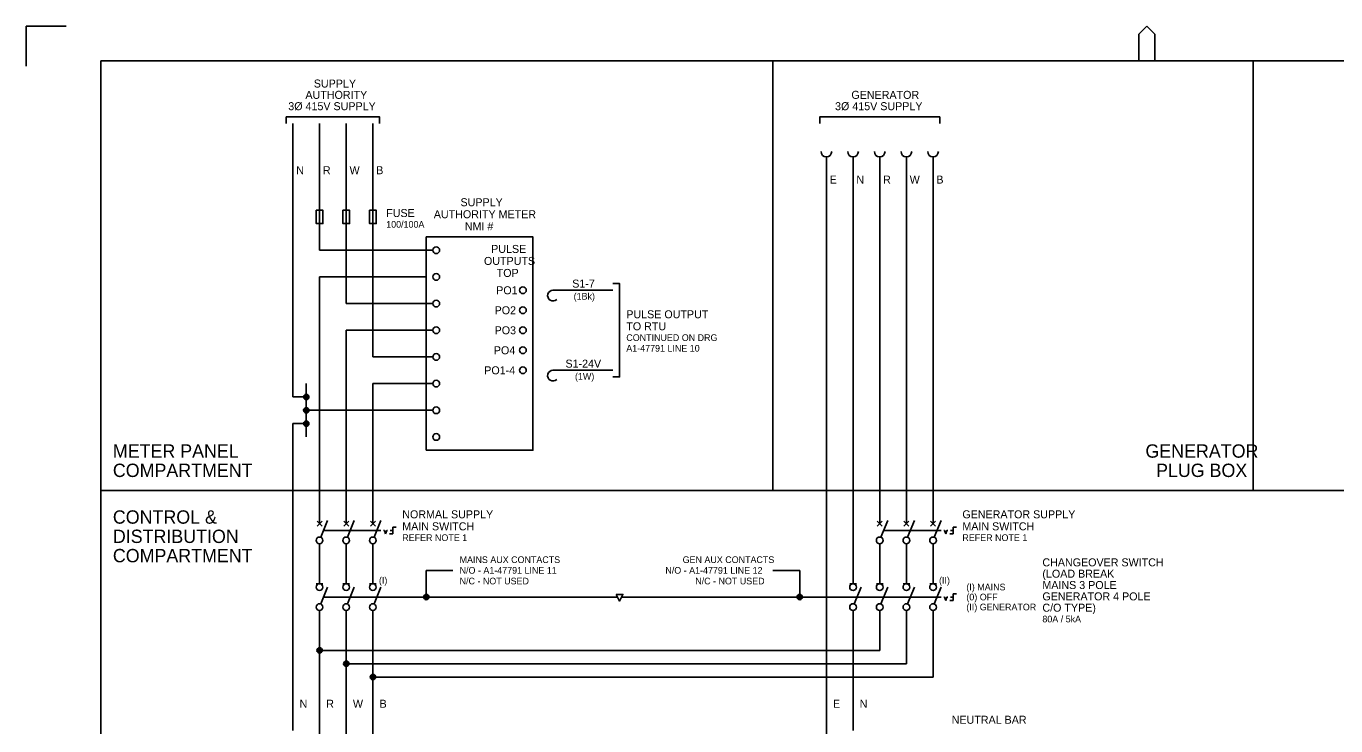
# Model space of a CAD drawing. Extents: x 0 to 841, y 0 to 594.
# Drawn here: x 0 to 491, y 331.7 to 594 of the extents above; entities that cross this region are included whole.
import ezdxf

# ---------------------------------------------------------------- set-up
doc = ezdxf.new("R2010")
doc.units = 0
for name, color, linetype in [('A1BORDER', 7, 'Continuous'), ('Level 1', 7, 'Continuous'), ('Level 10', 7, 'Continuous')]:
    doc.layers.add(name, color=color, linetype=linetype)

msp = doc.modelspace()

# ---------------------------------------------------------------- linework, layer by layer
at = {"layer": 'A1BORDER'}
for p, q in [((0, 594), (15, 594)), ((0, 579), (0, 594)), ((417.19, 591), (420.19, 594)), ((417.19, 581), (417.19, 591)), ((423.19, 591), (420.19, 594)), ((423.19, 581), (423.19, 591)), ((28, 581), (829, 581)), ((28, 581), (28, 15))]:
    msp.add_line(p, q, dxfattribs=at)
at = {"layer": 'Level 1'}
for p, q in [((280, 420), (280, 581)), ((460, 420), (460, 581)), ((100, 455), (100, 557.5)), ((110, 510), (110, 557.5)), ((120, 490), (120, 557.5)), ((130, 470), (130, 557.5)), ((300, 320), (300, 545)), ((310, 385), (310, 545)), ((320, 410), (320, 545)), ((330, 410), (330, 545)), ((340, 410), (340, 545)), ((153.75, 511.25), (153.75, 511.25)), ((152.5, 510), (110, 510)), ((153.75, 508.75), (153.75, 508.75)), ((153.75, 501.25), (153.75, 501.25)), ((150, 500), (110, 500)), ((110, 500), (110, 410)), ((153.75, 498.75), (153.75, 498.75)), ((186.25, 496.25), (186.25, 496.25)), ((153.75, 491.25), (153.75, 491.25)), ((186.25, 493.75), (186.25, 493.75)), ((197.5, 495), (220, 495)), ((152.5, 490), (120, 490)), ((153.75, 488.75), (153.75, 488.75)), ((186.25, 488.75), (186.25, 488.75)), ((186.25, 486.25), (186.25, 486.25)), ((153.75, 481.25), (153.75, 481.25)), ((186.25, 481.25), (186.25, 481.25)), ((152.5, 480), (120, 480)), ((120, 480), (120, 410)), ((153.75, 478.75), (153.75, 478.75)), ((186.25, 478.75), (186.25, 478.75)), ((186.25, 473.75), (186.25, 473.75)), ((152.5, 470), (130, 470)), ((153.75, 471.25), (153.75, 471.25)), ((153.75, 468.75), (153.75, 468.75)), ((186.25, 471.25), (186.25, 471.25)), ((186.25, 466.25), (186.25, 466.25)), ((186.25, 463.75), (186.25, 463.75)), ((197.5, 465), (220, 465)), ((105, 460), (105, 440)), ((152.5, 460), (130, 460)), ((130, 460), (130, 410)), ((153.75, 461.25), (153.75, 461.25)), ((153.75, 458.75), (153.75, 458.75)), ((100, 455), (105, 455)), ((152.5, 450), (105, 450)), ((153.75, 451.25), (153.75, 451.25)), ((153.75, 448.75), (153.75, 448.75)), ((100, 330), (100, 445)), ((105, 445), (100, 445)), ((153.75, 441.25), (153.75, 441.25)), ((153.75, 438.75), (153.75, 438.75)), ((28, 420), (829, 420)), ((109.06, 408.44), (110.94, 406.56)), ((110.94, 408.44), (109.06, 406.56)), ((110, 407.5), (110, 410)), ((110.46, 402.41), (113, 408.75)), ((119.06, 408.44), (120.94, 406.56)), ((120.94, 408.44), (119.06, 406.56)), ((120, 407.5), (120, 410)), ((120.46, 402.41), (123, 408.75)), ((129.06, 408.44), (130.94, 406.56)), ((130.94, 408.44), (129.06, 406.56)), ((130, 407.5), (130, 410)), ((130.46, 402.41), (133, 408.75)), ((319.06, 408.44), (320.94, 406.56)), ((320.94, 408.44), (319.06, 406.56)), ((320, 407.5), (320, 410)), ((320.46, 402.41), (323, 408.75)), ((329.06, 408.44), (330.94, 406.56)), ((330.94, 408.44), (329.06, 406.56)), ((330, 407.5), (330, 410)), ((330.46, 402.41), (333, 408.75)), ((339.06, 408.44), (340.94, 406.56)), ((340.94, 408.44), (339.06, 406.56)), ((340, 407.5), (340, 410)), ((340.46, 402.41), (343, 408.75)), ((111.5, 405), (131.5, 405)), ((321.5, 405), (341.5, 405)), ((110, 400), (110, 385)), ((120, 400), (120, 385)), ((130, 400), (130, 385)), ((320, 400), (320, 385)), ((330, 400), (330, 385)), ((340, 400), (340, 385)), ((150, 380), (150, 390)), ((150, 390), (160, 390)), ((280, 390), (290, 390)), ((290, 380), (290, 390)), ((108.75, 385), (111.25, 385)), ((110.46, 377.41), (113, 383.75)), ((118.75, 385), (121.25, 385)), ((120.46, 377.41), (123, 383.75)), ((128.75, 385), (131.25, 385)), ((130.46, 377.41), (133, 383.75)), ((308.75, 385), (311.25, 385)), ((310.46, 377.41), (313, 383.75)), ((318.75, 385), (321.25, 385)), ((320.46, 377.41), (323, 383.75)), ((328.75, 385), (331.25, 385)), ((330.46, 377.41), (333, 383.75)), ((338.75, 385), (341.25, 385)), ((340.46, 377.41), (343, 383.75)), ((111.5, 380), (221.75, 380)), ((149.01, 380.1), (150.99, 380.1)), ((149.02, 379.8), (150.98, 379.8)), ((149.08, 380.4), (150.92, 380.4)), ((149.13, 379.5), (150.87, 379.5)), ((149.29, 380.7), (150.71, 380.7)), ((149.4, 379.2), (150.6, 379.2)), ((150, 381), (150, 381)), ((223.25, 380), (341.5, 380)), ((289.01, 380.1), (290.99, 380.1)), ((289.02, 379.8), (290.98, 379.8)), ((289.08, 380.4), (290.92, 380.4)), ((289.13, 379.5), (290.87, 379.5)), ((289.29, 380.7), (290.71, 380.7)), ((289.4, 379.2), (290.6, 379.2)), ((290, 381), (290, 381)), ((110, 375), (110, 310)), ((120, 375), (120, 300)), ((130, 375), (130, 290)), ((310, 330), (310, 375)), ((320, 360), (320, 375)), ((330, 355), (330, 375)), ((340, 350), (340, 375)), ((109.01, 360.1), (110.99, 360.1)), ((109.02, 359.8), (110.98, 359.8)), ((109.08, 360.4), (110.92, 360.4)), ((109.13, 359.5), (110.87, 359.5)), ((109.29, 360.7), (110.71, 360.7)), ((109.4, 359.2), (110.6, 359.2)), ((110, 361), (110, 361)), ((320, 360), (110, 360)), ((119.01, 355.1), (120.99, 355.1)), ((119.02, 354.8), (120.98, 354.8)), ((119.08, 355.4), (120.92, 355.4)), ((119.13, 354.5), (120.87, 354.5)), ((119.29, 355.7), (120.71, 355.7)), ((119.4, 354.2), (120.6, 354.2)), ((120, 356), (120, 356)), ((120, 355), (330, 355)), ((129.01, 350.1), (130.99, 350.1)), ((129.02, 349.8), (130.98, 349.8)), ((129.08, 350.4), (130.92, 350.4)), ((129.13, 349.5), (130.87, 349.5)), ((129.29, 350.7), (130.71, 350.7)), ((129.4, 349.2), (130.6, 349.2)), ((130, 351), (130, 351)), ((130, 350), (340, 350))]:
    msp.add_line(p, q, dxfattribs=at)
for points in [[(97.5, 557.5), (97.5, 560), (132.5, 560), (132.5, 557.5)], [(297.5, 557.5), (297.5, 560), (342.5, 560), (342.5, 557.5)], [(220, 497.5), (222.5, 497.5), (222.5, 462.5), (220, 462.5)]]:
    msp.add_lwpolyline(points, dxfattribs=at)
for points in [[(150, 435), (190, 435), (190, 515), (150, 515)], [(221.25, 381), (222.5, 378.5), (223.75, 381)]]:
    msp.add_lwpolyline(points, close=True, dxfattribs=at)
for centre, radius in [((110, 401.25), 1.25), ((120, 401.25), 1.25), ((130, 401.25), 1.25), ((320, 401.25), 1.25), ((330, 401.25), 1.25), ((340, 401.25), 1.25), ((110, 383.75), 1.25), ((120, 383.75), 1.25), ((130, 383.75), 1.25), ((310, 383.75), 1.25), ((320, 383.75), 1.25), ((330, 383.75), 1.25), ((340, 383.75), 1.25), ((150, 380), 1), ((290, 380), 1), ((110, 376.25), 1.25), ((120, 376.25), 1.25), ((130, 376.25), 1.25), ((310, 376.25), 1.25), ((320, 376.25), 1.25), ((330, 376.25), 1.25), ((340, 376.25), 1.25), ((110, 360), 1), ((120, 355), 1), ((130, 350), 1)]:
    msp.add_circle(centre, radius, dxfattribs=at)
for centre in [(197.5, 493), (197.5, 463)]:
    msp.add_arc(centre, 2, 90, 315, dxfattribs=at)
at = {"layer": 'Level 10'}
for p, q in [((104.01, 455.1), (105.99, 455.1)), ((104.02, 454.8), (105.98, 454.8)), ((104.08, 455.4), (105.92, 455.4)), ((104.13, 454.5), (105.87, 454.5)), ((104.29, 455.7), (105.71, 455.7)), ((104.4, 454.2), (105.6, 454.2)), ((105, 456), (105, 456)), ((104.01, 450.1), (105.99, 450.1)), ((104.02, 449.8), (105.98, 449.8)), ((104.08, 450.4), (105.92, 450.4)), ((104.13, 449.5), (105.87, 449.5)), ((104.29, 450.7), (105.71, 450.7)), ((104.4, 449.2), (105.6, 449.2)), ((105, 451), (105, 451)), ((104.01, 445.1), (105.99, 445.1)), ((104.02, 444.8), (105.98, 444.8)), ((104.08, 445.4), (105.92, 445.4)), ((104.13, 444.5), (105.87, 444.5)), ((104.29, 445.7), (105.71, 445.7)), ((104.4, 444.2), (105.6, 444.2)), ((105, 446), (105, 446)), ((131.5, 405), (133, 405)), ((134, 405), (134.33, 405)), ((134.75, 403.75), (134.33, 405)), ((134.75, 403.75), (135.17, 405)), ((135.5, 405), (135.17, 405)), ((136.25, 403.75), (137.5, 403.75)), ((136.5, 405), (137.5, 405)), ((137.5, 403.75), (137.5, 406.25)), ((137.5, 406.25), (138.75, 406.25)), ((341.5, 405), (343, 405)), ((344, 405), (344.33, 405)), ((344.75, 403.75), (344.33, 405)), ((344.75, 403.75), (345.17, 405)), ((345.5, 405), (345.17, 405)), ((346.25, 403.75), (347.5, 403.75)), ((346.5, 405), (347.5, 405)), ((347.5, 403.75), (347.5, 406.25)), ((347.5, 406.25), (348.75, 406.25)), ((341.5, 380), (343, 380)), ((344, 380), (344.33, 380)), ((344.75, 378.75), (344.33, 380)), ((344.75, 378.75), (345.17, 380)), ((345.5, 380), (345.17, 380)), ((346.25, 378.75), (347.5, 378.75)), ((346.5, 380), (347.5, 380)), ((347.5, 378.75), (347.5, 381.25)), ((347.5, 381.25), (348.75, 381.25))]:
    msp.add_line(p, q, dxfattribs=at)
for points in [[(110, 520), (111.25, 520), (111.25, 525), (108.75, 525), (108.75, 520), (110, 520)], [(120, 520), (121.25, 520), (121.25, 525), (118.75, 525), (118.75, 520), (120, 520)], [(130, 520), (131.25, 520), (131.25, 525), (128.75, 525), (128.75, 520), (130, 520)]]:
    msp.add_lwpolyline(points, dxfattribs=at)
for centre, radius in [((153.75, 510), 1.25), ((153.75, 500), 1.25), ((186.25, 495), 1.25), ((153.75, 490), 1.25), ((186.25, 487.5), 1.25), ((153.75, 480), 1.25), ((186.25, 480), 1.25), ((186.25, 472.5), 1.25), ((153.75, 470), 1.25), ((186.25, 465), 1.25), ((153.75, 460), 1.25), ((105, 455), 1), ((105, 450), 1), ((153.75, 450), 1.25), ((105, 445), 1), ((153.75, 440), 1.25)]:
    msp.add_circle(centre, radius, dxfattribs=at)
for centre in [(300, 547), (310, 547), (320, 547), (330, 547), (340, 547)]:
    msp.add_arc(centre, 2, 180, 0, dxfattribs=at)

# ---------------------------------------------------------------- texts
at = {"layer": 'Level 1'}
for s, height, p in [('AUTHORITY', 3, (104.69, 566.76)), ('SUPPLY', 3, (107.83, 571.01)), ('GENERATOR', 3, (309.39, 566.76)), ('3Ø 415V SUPPLY', 3, (98.27, 562.51)), ('3Ø 415V SUPPLY', 3, (303.27, 562.51)), ('N', 3, (101.25, 538.5)), ('R', 3, (111.25, 538.5)), ('W', 3, (121.25, 538.5)), ('B', 3, (131.25, 538.5)), ('E', 3, (301.25, 535)), ('N', 3, (311.25, 535)), ('R', 3, (321.25, 535)), ('W', 3, (331.25, 535)), ('B', 3, (341.25, 535)), ('FUSE', 3, (134.98, 522.46)), ('SUPPLY', 3, (162.83, 526.5)), ('100/100A', 2.5, (134.98, 518.46)), ('AUTHORITY METER', 3, (152.82, 522)), ('NMI #', 3, (164.47, 517.5)), ('PULSE', 3, (174.32, 509)), ('OUTPUTS', 3, (171.63, 504.5)), ('TOP', 3, (176.41, 500)), ('PO1', 3, (176.22, 493.5)), ('S1-7', 3, (204.72, 496)), ('(1Bk)', 2.5, (205.26, 491.5)), ('PO2', 3, (175.63, 486)), ('PULSE OUTPUT', 3, (225, 484.5)), ('PO3', 3, (175.63, 478.5)), ('TO RTU', 3, (225, 480)), ('CONTINUED ON DRG', 2.5, (225, 476)), ('PO4', 3, (175.33, 471)), ('A1-47791 LINE 10', 2.5, (225, 472)), ('PO1-4', 3, (171.74, 463.5)), ('S1-24V', 3, (202.18, 466)), ('(1W)', 2.5, (205.76, 461.5)), ('METER PANEL', 5, (32.5, 432.24)), ('GENERATOR', 5, (419.64, 432.24)), ('COMPARTMENT', 5, (32.5, 425)), ('PLUG BOX', 5, (423.62, 425)), ('CONTROL &', 5, (32.5, 407.5)), ('NORMAL SUPPLY', 3, (141, 409.51)), ('GENERATOR SUPPLY', 3, (351, 409.51)), ('MAIN SWITCH', 3, (141, 405.01)), ('MAIN SWITCH', 3, (351, 405.01)), ('DISTRIBUTION', 5, (32.5, 400.26)), ('REFER NOTE 1', 2.5, (141, 401)), ('REFER NOTE 1', 2.5, (351, 401)), ('COMPARTMENT', 5, (32.5, 393.03)), ('MAINS AUX CONTACTS', 2.5, (162.5, 392.75)), ('GEN AUX CONTACTS', 2.5, (246.12, 392.75)), ('CHANGEOVER SWITCH', 3, (381, 391.5)), ('N/O - A1-47791 LINE 11', 2.5, (162.5, 388.75)), ('N/O - A1-47791 LINE 12', 2.5, (239.65, 388.75)), ('(LOAD BREAK', 3, (381, 387.25)), ('(I)', 2.5, (132.25, 385)), ('N/C - NOT USED', 2.5, (162.5, 384.75)), ('N/C - NOT USED', 2.5, (250.85, 384.75)), ('(II)', 2.5, (342.25, 385)), ('(I) MAINS', 2.5, (352.5, 382.5)), ('MAINS 3 POLE', 3, (381, 383)), ('(0) OFF', 2.5, (352.5, 378.75)), ('GENERATOR 4 POLE', 3, (381, 378.75)), ('(II) GENERATOR', 2.5, (352.5, 375)), ('C/O TYPE)', 3, (381, 374.5)), ('80A / 5kA', 2.5, (381, 370.5)), ('N', 3, (102.5, 338.5)), ('R', 3, (112.5, 338.5)), ('W', 3, (122.5, 338.5)), ('B', 3, (132.5, 338.5)), ('E', 3, (302.5, 338.5)), ('N', 3, (312.5, 338.5)), ('NEUTRAL BAR', 3, (347, 332.5))]:
    msp.add_text(s, height=height, dxfattribs=at).set_placement(p)

doc.saveas('drawing.dxf')
